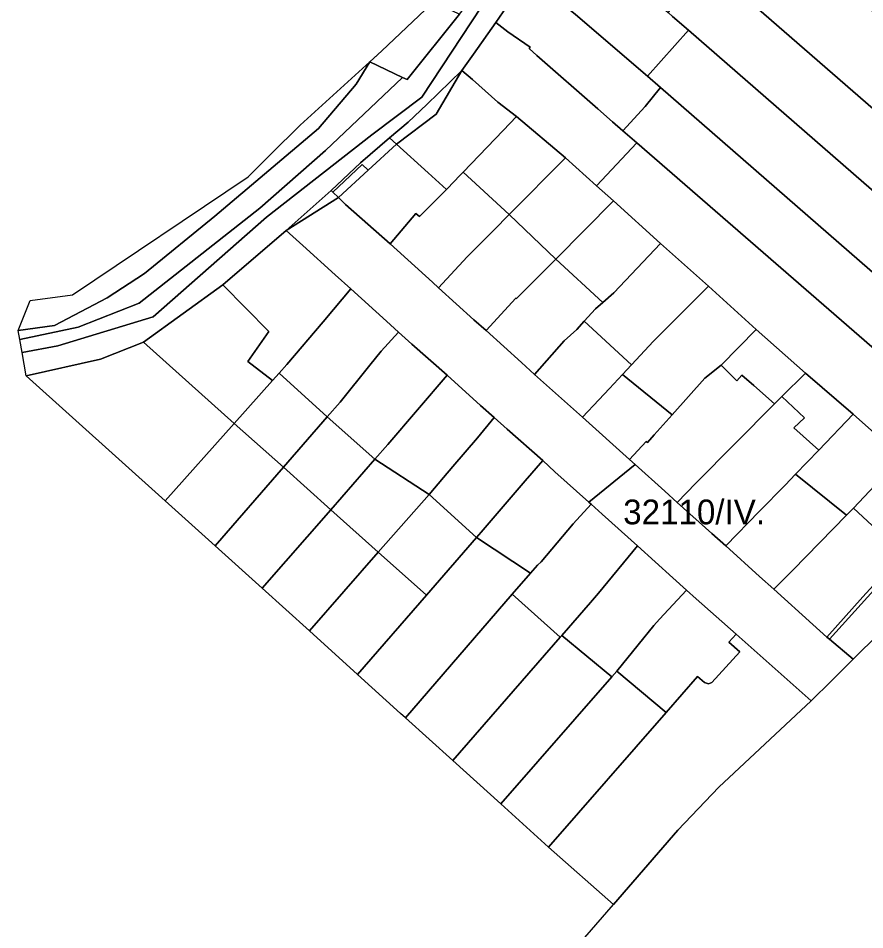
# Model space of a CAD drawing. Extents: x -537068 to -534056, y -1176840 to -1172401.
# Drawn here: x -536869.7 to -536698.9, y -1175812 to -1175628 of the extents above; entities that cross this region are included whole.
import ezdxf

# ---------------------------------------------------------------- set-up
doc = ezdxf.new("R2010")
doc.units = 0
for name, color, linetype in [('95590013', 7, 'Continuous'), ('95640013', 7, 'Continuous'), ('95660013', 7, 'Continuous')]:
    doc.layers.add(name, color=color, linetype=linetype)

msp = doc.modelspace()

# ---------------------------------------------------------------- linework, layer by layer
at = {"layer": '95590013'}
for points in [[(-536729.03, -1175618.55), (-536723.45, -1175612.71), (-536718.97, -1175607.55), (-536716.48, -1175609.73), (-536694.41, -1175629.09), (-536665.73, -1175653.71), (-536677.69, -1175663.21)], [(-536738.58, -1175626.8), (-536736.64, -1175624.57), (-536730.43, -1175617.33), (-536729.03, -1175618.55), (-536677.69, -1175663.21), (-536687.67, -1175671.13), (-536734.49, -1175630.36), (-536737.67, -1175627.59)], [(-536663.98, -1175708.29), (-536740.09, -1175641.93), (-536742.73, -1175639.67), (-536734.49, -1175630.36), (-536687.67, -1175671.13), (-536655.21, -1175699.39)], [(-536663.98, -1175708.29), (-536672.01, -1175716.43), (-536744.88, -1175653.12), (-536747.7, -1175650.69), (-536743.23, -1175645.78), (-536740.09, -1175641.93)], [(-536770.64, -1175667.62), (-536779.9, -1175659.02), (-536771.88, -1175650.63), (-536769.19, -1175647.81), (-536759.27, -1175656.16)], [(-536744.88, -1175653.12), (-536672.01, -1175716.43), (-536680.13, -1175724.67), (-536681.09, -1175725.73), (-536691.5, -1175716.6), (-536701.24, -1175707.9), (-536710.86, -1175699.62), (-536720.78, -1175690.83), (-536730.4, -1175682.06), (-536740.09, -1175673.41), (-536749.56, -1175664.85), (-536753, -1175661.78)], [(-536770.64, -1175667.62), (-536759.27, -1175656.16), (-536753, -1175661.78), (-536749.56, -1175664.85), (-536761.21, -1175676.58)], [(-536749.56, -1175664.85), (-536740.09, -1175673.41), (-536749.5, -1175683.41), (-536751.75, -1175685.34), (-536761.21, -1175676.58)], [(-536749.5, -1175683.41), (-536740.09, -1175673.41), (-536730.4, -1175682.06), (-536741.49, -1175693.19), (-536745.93, -1175697.91), (-536755.52, -1175689.13), (-536753.25, -1175686.62), (-536751.75, -1175685.34)], [(-536818.36, -1175701.11), (-536826.1, -1175709.76), (-536844.44, -1175693.33), (-536828.39, -1175681.76), (-536819.16, -1175691.2), (-536823.36, -1175697.24)], [(-536737.75, -1175708.04), (-536747.77, -1175699.87), (-536745.93, -1175697.91), (-536741.49, -1175693.19), (-536730.4, -1175682.06), (-536720.78, -1175690.83), (-536727.9, -1175698), (-536731.14, -1175700.63)], [(-536710.86, -1175699.62), (-536715.63, -1175704.3), (-536717.1, -1175705.79), (-536721.3, -1175702.09), (-536723.73, -1175700.05), (-536724.68, -1175701.18), (-536727.9, -1175698), (-536720.78, -1175690.83)], [(-536844.44, -1175693.33), (-536826.1, -1175709.76), (-536840.08, -1175725.38), (-536868.06, -1175700.18), (-536853.12, -1175696.82)], [(-536817.02, -1175699.61), (-536807.37, -1175708.47), (-536816.2, -1175718.62), (-536826.1, -1175709.76), (-536818.36, -1175701.11)], [(-536701.24, -1175707.9), (-536708.19, -1175715.14), (-536713.19, -1175710.67), (-536711.09, -1175708.62), (-536715.63, -1175704.3), (-536710.86, -1175699.62)], [(-536691.5, -1175716.6), (-536701.19, -1175726.88), (-536702.6, -1175728.32), (-536712.9, -1175720.04), (-536708.19, -1175715.14), (-536701.24, -1175707.9)], [(-536816.2, -1175718.62), (-536829.96, -1175734.45), (-536840.08, -1175725.38), (-536826.1, -1175709.76)], [(-536807.37, -1175708.47), (-536797.74, -1175717.01), (-536806.63, -1175727.19), (-536816.2, -1175718.62)], [(-536797.74, -1175717.01), (-536786.81, -1175724.09), (-536797.05, -1175735.77), (-536806.63, -1175727.19)], [(-536691.3, -1175736.01), (-536697.43, -1175730.35), (-536701.19, -1175726.88), (-536691.5, -1175716.6), (-536681.09, -1175725.73), (-536706, -1175753.35), (-536706.53, -1175752.91), (-536699.29, -1175744.78)], [(-536816.2, -1175718.62), (-536806.63, -1175727.19), (-536820.47, -1175743.03), (-536829.96, -1175734.45)], [(-536786.81, -1175724.09), (-536777.26, -1175732.83), (-536787.35, -1175744.45), (-536797.05, -1175735.77)], [(-536674.81, -1175731.24), (-536701.22, -1175757.38), (-536706, -1175753.35), (-536681.09, -1175725.73)], [(-536820.47, -1175743.03), (-536806.63, -1175727.19), (-536797.05, -1175735.77), (-536810.95, -1175751.62)], [(-536801.26, -1175760.46), (-536787.35, -1175744.45), (-536777.26, -1175732.83), (-536766.33, -1175740.03), (-536770.01, -1175744.27), (-536791.57, -1175769.17), (-536792.54, -1175768.3)], [(-536810.95, -1175751.62), (-536797.05, -1175735.77), (-536787.35, -1175744.45), (-536801.26, -1175760.46)], [(-536760.34, -1175752.93), (-536781.98, -1175777.85), (-536791.57, -1175769.17), (-536770.01, -1175744.27)], [(-536749.94, -1175760.9), (-536772.3, -1175786.55), (-536781.98, -1175777.85), (-536760.34, -1175752.93), (-536760.01, -1175752.55)], [(-536724.1, -1175755.88), (-536726.31, -1175753.91), (-536724.85, -1175752.34), (-536709.68, -1175765.75), (-536728.37, -1175783.23), (-536736.63, -1175791.89), (-536749.56, -1175806.92), (-536762.69, -1175795.33), (-536738.97, -1175768.13), (-536732.63, -1175760.86), (-536731.25, -1175762.08), (-536730.42, -1175762.35), (-536729.72, -1175762.05)], [(-536762.69, -1175795.33), (-536772.3, -1175786.55), (-536749.94, -1175760.9), (-536748.95, -1175759.77), (-536738.97, -1175768.13)]]:
    msp.add_lwpolyline(points, close=True, dxfattribs=at)
at = {"layer": '95640013'}
for points in [[(-536742.83, -1175623.1), (-536738.58, -1175626.8), (-536737.67, -1175627.59), (-536734.49, -1175630.36), (-536742.73, -1175639.67), (-536757.26, -1175627.21), (-536763.97, -1175621.61), (-536766.93, -1175619.43), (-536764.75, -1175616.19), (-536759.8, -1175608.87), (-536756.64, -1175611.7), (-536752.17, -1175614.97)], [(-536820.95, -1175666.33), (-536807.7, -1175654.66), (-536792.15, -1175639.9), (-536791.22, -1175640.34), (-536780.67, -1175627.12), (-536778.85, -1175624.83), (-536774.37, -1175617.09), (-536774.21, -1175622.47), (-536788.24, -1175643.89), (-536798.36, -1175651.52), (-536819.62, -1175668.1), (-536842.48, -1175688.23), (-536861.71, -1175694.13), (-536868.9, -1175695.44), (-536869.36, -1175692.85), (-536857.62, -1175690.33), (-536845.3, -1175685.5)], [(-536749.78, -1175648.9), (-536752.78, -1175646.25), (-536765.03, -1175635.47), (-536766.63, -1175634.09), (-536766.43, -1175633.83), (-536770.89, -1175630.74), (-536773.32, -1175628.81), (-536771.12, -1175625.57), (-536766.93, -1175619.43), (-536763.97, -1175621.61), (-536757.26, -1175627.21), (-536742.73, -1175639.67), (-536740.09, -1175641.93), (-536743.23, -1175645.78), (-536747.7, -1175650.69)], [(-536786.55, -1175624.33), (-536780.67, -1175627.12), (-536791.22, -1175640.34), (-536792.15, -1175639.9), (-536798.75, -1175636.8), (-536796.36, -1175634.54), (-536787.59, -1175626.26)], [(-536766.63, -1175634.09), (-536765.03, -1175635.47), (-536752.78, -1175646.25), (-536749.78, -1175648.9), (-536747.7, -1175650.69), (-536744.88, -1175653.12), (-536753, -1175661.78), (-536759.27, -1175656.16), (-536769.19, -1175647.81), (-536772.91, -1175644.94), (-536778.02, -1175640.31), (-536780.16, -1175638.55), (-536777.81, -1175635.2), (-536773.32, -1175628.81), (-536770.89, -1175630.74), (-536766.43, -1175633.83)], [(-536809.14, -1175650.25), (-536830.05, -1175667.93), (-536844.21, -1175679.47), (-536851.74, -1175684.41), (-536862.39, -1175690.01), (-536869.69, -1175690.99), (-536867.27, -1175684.92), (-536858.75, -1175683.8), (-536823.33, -1175660), (-536822.48, -1175659.15), (-536818.75, -1175655.44), (-536812.82, -1175649.52), (-536798.75, -1175636.8), (-536801.52, -1175641.28)], [(-536869.36, -1175692.85), (-536869.69, -1175690.99), (-536862.39, -1175690.01), (-536851.74, -1175684.41), (-536844.21, -1175679.47), (-536830.05, -1175667.93), (-536809.14, -1175650.25), (-536801.52, -1175641.28), (-536798.75, -1175636.8), (-536792.15, -1175639.9), (-536807.7, -1175654.66), (-536820.95, -1175666.33), (-536845.3, -1175685.5), (-536857.62, -1175690.33)], [(-536785.35, -1175647.31), (-536793.35, -1175653.37), (-536794.76, -1175652.08), (-536791.04, -1175648.95), (-536787.27, -1175645.35), (-536780.16, -1175638.55)], [(-536783.26, -1175662.54), (-536786.98, -1175659.17), (-536793.35, -1175653.37), (-536785.35, -1175647.31), (-536780.16, -1175638.55), (-536778.02, -1175640.31), (-536772.91, -1175644.94), (-536769.19, -1175647.81), (-536771.88, -1175650.63), (-536779.9, -1175659.02), (-536780.5, -1175659.65), (-536783.14, -1175662.42)], [(-536800.66, -1175657.18), (-536794.76, -1175652.08), (-536793.35, -1175653.37), (-536799.08, -1175658.65), (-536800.29, -1175657.52), (-536806.21, -1175663.08), (-536806.57, -1175662.74)], [(-536805.07, -1175664.17), (-536799.08, -1175658.65), (-536793.35, -1175653.37), (-536786.98, -1175659.17), (-536783.26, -1175662.54), (-536788.76, -1175668.01), (-536789.48, -1175667.39), (-536794.65, -1175673.53), (-536803.64, -1175665.54)], [(-536806.21, -1175663.08), (-536800.29, -1175657.52), (-536799.08, -1175658.65), (-536805.07, -1175664.17)], [(-536770.64, -1175667.62), (-536773.75, -1175670.75), (-536779.1, -1175676.14), (-536784.91, -1175682.36), (-536786.11, -1175681.27), (-536794.65, -1175673.53), (-536789.48, -1175667.39), (-536788.76, -1175668.01), (-536783.26, -1175662.54), (-536783.14, -1175662.42), (-536780.5, -1175659.65), (-536779.9, -1175659.02)], [(-536806.57, -1175662.74), (-536806.21, -1175663.08), (-536805.07, -1175664.17), (-536815.65, -1175670.79), (-536815.02, -1175670.25)], [(-536773.69, -1175708.6), (-536776.41, -1175706.14), (-536783.16, -1175700.01), (-536790.25, -1175693.76), (-536792.96, -1175691.36), (-536795.41, -1175689.13), (-536802.59, -1175682.62), (-536805.72, -1175679.78), (-536812.27, -1175673.86), (-536815.65, -1175670.79), (-536805.07, -1175664.17), (-536803.64, -1175665.54), (-536794.65, -1175673.53), (-536786.11, -1175681.27), (-536784.91, -1175682.36), (-536777.74, -1175688.84), (-536775.31, -1175691.04), (-536768.18, -1175697.45), (-536765.5, -1175699.86), (-536755.85, -1175708.53), (-536746.34, -1175717.05), (-536745.23, -1175718.05), (-536754.56, -1175725.69), (-536761.41, -1175719.51), (-536763.88, -1175717.28), (-536771.05, -1175710.94)], [(-536779.1, -1175676.14), (-536773.75, -1175670.75), (-536770.64, -1175667.62), (-536761.21, -1175676.58), (-536762.68, -1175678.06), (-536769.16, -1175684.58), (-536769.28, -1175684.49), (-536775.31, -1175691.04), (-536777.74, -1175688.84), (-536784.91, -1175682.36)], [(-536808.2, -1175689.26), (-536815.52, -1175697.84), (-536817.02, -1175699.61), (-536818.36, -1175701.11), (-536823.36, -1175697.24), (-536819.16, -1175691.2), (-536828.39, -1175681.76), (-536815.65, -1175670.79), (-536812.27, -1175673.86), (-536805.72, -1175679.78), (-536802.59, -1175682.62), (-536806.09, -1175686.79)], [(-536759.53, -1175693.11), (-536765.5, -1175699.86), (-536768.18, -1175697.45), (-536775.31, -1175691.04), (-536769.28, -1175684.49), (-536769.16, -1175684.58), (-536762.68, -1175678.06), (-536761.21, -1175676.58), (-536751.75, -1175685.34), (-536753.25, -1175686.62), (-536755.52, -1175689.13), (-536757.02, -1175690.8)], [(-536806.09, -1175686.79), (-536802.59, -1175682.62), (-536795.41, -1175689.13), (-536792.96, -1175691.36), (-536796.47, -1175695.21), (-536798.73, -1175698.01), (-536804.74, -1175705.45), (-536807.37, -1175708.47), (-536817.02, -1175699.61), (-536815.52, -1175697.84), (-536808.2, -1175689.26)], [(-536750.43, -1175702.7), (-536752.54, -1175705), (-536755.85, -1175708.53), (-536765.5, -1175699.86), (-536759.53, -1175693.11), (-536757.02, -1175690.8), (-536755.52, -1175689.13), (-536745.93, -1175697.91), (-536747.77, -1175699.87)], [(-536798.73, -1175698.01), (-536796.47, -1175695.21), (-536792.96, -1175691.36), (-536790.25, -1175693.76), (-536783.16, -1175700.01), (-536795.1, -1175713.99), (-536797.74, -1175717.01), (-536807.37, -1175708.47), (-536804.74, -1175705.45)], [(-536746.34, -1175717.05), (-536742.97, -1175713.44), (-536742.75, -1175713.64), (-536741.36, -1175712.08), (-536737.75, -1175708.04), (-536731.14, -1175700.63), (-536727.9, -1175698), (-536724.68, -1175701.18), (-536723.73, -1175700.05), (-536721.3, -1175702.09), (-536717.1, -1175705.79), (-536732.98, -1175721.85), (-536736.75, -1175725.73), (-536739.26, -1175723.46), (-536745.23, -1175718.05)], [(-536783.16, -1175700.01), (-536776.41, -1175706.14), (-536773.69, -1175708.6), (-536777.03, -1175712.65), (-536781.98, -1175718.44), (-536783.92, -1175720.71), (-536786.81, -1175724.09), (-536797.74, -1175717.01), (-536795.1, -1175713.99)], [(-536742.75, -1175713.64), (-536742.97, -1175713.44), (-536746.34, -1175717.05), (-536755.85, -1175708.53), (-536752.54, -1175705), (-536750.43, -1175702.7), (-536747.77, -1175699.87), (-536737.75, -1175708.04), (-536741.36, -1175712.08)], [(-536726.9, -1175734.47), (-536729.73, -1175731.96), (-536736.75, -1175725.73), (-536732.98, -1175721.85), (-536717.1, -1175705.79), (-536715.63, -1175704.3), (-536711.09, -1175708.62), (-536713.19, -1175710.67), (-536708.19, -1175715.14), (-536712.9, -1175720.04), (-536714.98, -1175722.22), (-536720.11, -1175727.45)], [(-536771.05, -1175710.94), (-536763.88, -1175717.28), (-536767.39, -1175721.38), (-536776.28, -1175731.7), (-536777.26, -1175732.83), (-536786.81, -1175724.09), (-536783.92, -1175720.71), (-536781.98, -1175718.44), (-536777.03, -1175712.65), (-536773.69, -1175708.6)], [(-536764.94, -1175738.37), (-536766.33, -1175740.03), (-536777.26, -1175732.83), (-536776.28, -1175731.7), (-536767.39, -1175721.38), (-536763.88, -1175717.28), (-536761.41, -1175719.51), (-536754.56, -1175725.69), (-536754.12, -1175726.09), (-536757.76, -1175730.04), (-536764.17, -1175737.74)], [(-536705.63, -1175761.74), (-536709.68, -1175765.75), (-536724.85, -1175752.34), (-536732.94, -1175745.15), (-536734.85, -1175743.46), (-536737.64, -1175740.95), (-536744.77, -1175734.51), (-536751.87, -1175728.12), (-536754.12, -1175726.09), (-536754.56, -1175725.69), (-536745.23, -1175718.05), (-536739.26, -1175723.46), (-536736.75, -1175725.73), (-536729.73, -1175731.96), (-536726.9, -1175734.47), (-536720.11, -1175740.64), (-536717.27, -1175743.22), (-536709.35, -1175750.36), (-536706.53, -1175752.91), (-536706, -1175753.35), (-536701.22, -1175757.38)], [(-536726.9, -1175734.47), (-536720.11, -1175727.45), (-536714.98, -1175722.22), (-536712.9, -1175720.04), (-536702.6, -1175728.32), (-536713.44, -1175739.36), (-536717.27, -1175743.22), (-536720.11, -1175740.64)], [(-536744.77, -1175734.51), (-536752.64, -1175744.01), (-536754.23, -1175745.9), (-536760.01, -1175752.55), (-536760.34, -1175752.93), (-536770.01, -1175744.27), (-536766.33, -1175740.03), (-536764.94, -1175738.37), (-536764.17, -1175737.74), (-536757.76, -1175730.04), (-536754.12, -1175726.09), (-536751.87, -1175728.12)], [(-536713.44, -1175739.36), (-536702.6, -1175728.32), (-536701.19, -1175726.88), (-536697.43, -1175730.35), (-536691.3, -1175736.01), (-536699.29, -1175744.78), (-536706.53, -1175752.91), (-536709.35, -1175750.36), (-536717.27, -1175743.22)], [(-536737.64, -1175740.95), (-536734.85, -1175743.46), (-536740.3, -1175749.27), (-536741.45, -1175750.59), (-536744.62, -1175754.46), (-536748.95, -1175759.77), (-536749.94, -1175760.9), (-536760.01, -1175752.55), (-536754.23, -1175745.9), (-536752.64, -1175744.01), (-536744.77, -1175734.51)], [(-536740.3, -1175749.27), (-536734.85, -1175743.46), (-536732.94, -1175745.15), (-536724.85, -1175752.34), (-536726.31, -1175753.91), (-536724.1, -1175755.88), (-536729.72, -1175762.05), (-536730.42, -1175762.35), (-536731.25, -1175762.08), (-536732.63, -1175760.86), (-536738.97, -1175768.13), (-536748.95, -1175759.77), (-536744.62, -1175754.46), (-536741.45, -1175750.59)]]:
    msp.add_lwpolyline(points, close=True, dxfattribs=at)
for points in [[(-536771.12, -1175625.57), (-536773.32, -1175628.81), (-536777.81, -1175635.2), (-536780.16, -1175638.55), (-536787.27, -1175645.35), (-536791.04, -1175648.95), (-536794.76, -1175652.08), (-536800.66, -1175657.18), (-536806.57, -1175662.74), (-536815.02, -1175670.25), (-536815.65, -1175670.79), (-536828.39, -1175681.76), (-536844.44, -1175693.33), (-536853.12, -1175696.82), (-536868.06, -1175700.18), (-536868.9, -1175695.44), (-536861.71, -1175694.13), (-536842.48, -1175688.23), (-536819.62, -1175668.1), (-536798.36, -1175651.52), (-536788.24, -1175643.89), (-536774.21, -1175622.47)], [(-536773.58, -1175834.53), (-536749.56, -1175806.92), (-536736.63, -1175791.89), (-536728.37, -1175783.23), (-536709.68, -1175765.75), (-536705.63, -1175761.74), (-536701.22, -1175757.38), (-536674.81, -1175731.24), (-536669.64, -1175725.77), (-536666.05, -1175721.61), (-536658.6, -1175712.98), (-536650.32, -1175703.64), (-536642.03, -1175694.23), (-536632.12, -1175682.89), (-536627.48, -1175677.77), (-536625.43, -1175668.78), (-536622.16, -1175654.48), (-536632.47, -1175639.06), (-536623.43, -1175623.26)]]:
    msp.add_lwpolyline(points, dxfattribs=at)
at = {"layer": '95660013'}
msp.add_lwpolyline([(-536773.58, -1175834.53), (-536749.56, -1175806.92), (-536762.69, -1175795.33), (-536772.3, -1175786.55), (-536781.98, -1175777.85), (-536791.57, -1175769.17), (-536792.54, -1175768.3), (-536801.26, -1175760.46), (-536810.95, -1175751.62), (-536820.47, -1175743.03), (-536829.96, -1175734.45), (-536840.08, -1175725.38), (-536868.06, -1175700.18), (-536868.9, -1175695.44), (-536869.36, -1175692.85), (-536869.69, -1175690.99), (-536867.27, -1175684.92), (-536858.75, -1175683.8), (-536823.33, -1175660), (-536822.48, -1175659.15), (-536818.75, -1175655.44), (-536812.82, -1175649.52), (-536798.75, -1175636.8), (-536798, -1175636.09), (-536796.36, -1175634.54), (-536787.59, -1175626.26)], dxfattribs=at)

# ---------------------------------------------------------------- texts
msp.add_text('32110/IV.', height=5, rotation=360, dxfattribs=at).set_placement((-536747.64, -1175730.14))

doc.saveas('drawing.dxf')
